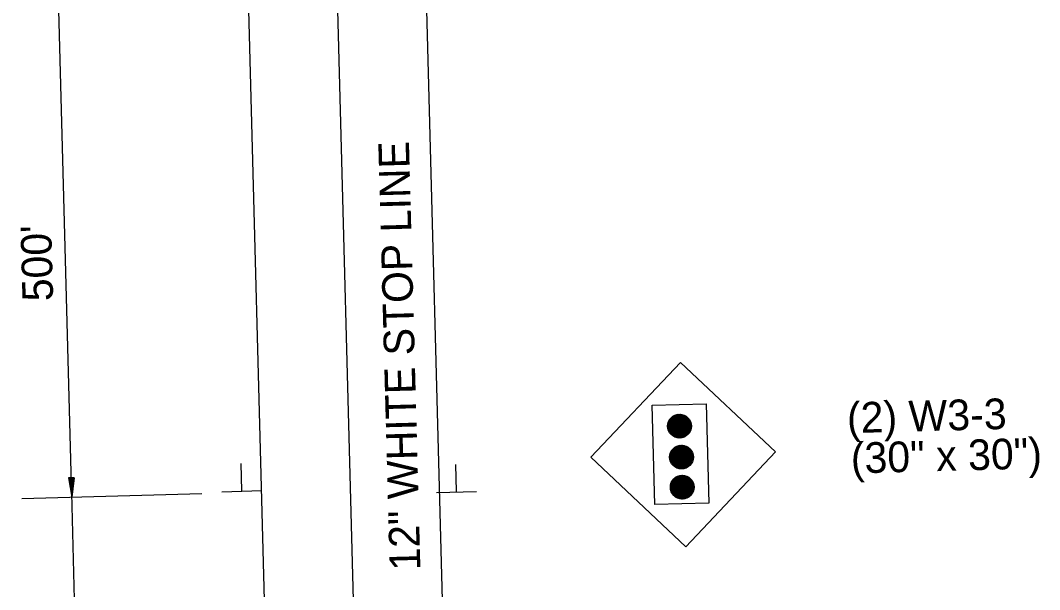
# Model space of a CAD drawing. Extents: x 1929624 to 1932070, y 596315 to 605533.
# Drawn here: x 1929776.5 to 1929980.4, y 598725.3 to 598839.2 of the extents above; entities that cross this region are included whole.
import ezdxf

# ---------------------------------------------------------------- set-up
doc = ezdxf.new("R2010")
doc.units = 0
doc.layers.add('Default', color=7, linetype='Continuous')

msp = doc.modelspace()

# ---------------------------------------------------------------- linework, layer by layer
at = {"layer": 'Default'}
for p, q in [((1929826.09, 598696.32), (1929821.7, 598859.91)), ((1929843.87, 598696.8), (1929839.48, 598860.38)), ((1929861.66, 598697.28), (1929857.27, 598860.86)), ((1929786.82, 598743.86), (1929784.11, 598844.96)), ((1929908.52, 598770.8), (1929890.6, 598751.83)), ((1929927.51, 598752.89), (1929908.52, 598770.8)), ((1929905.96, 598758.03), (1929908.25, 598760.44)), ((1929905.96, 598758.18), (1929908.09, 598760.43)), ((1929905.97, 598757.88), (1929908.39, 598760.44)), ((1929905.98, 598757.75), (1929908.53, 598760.43)), ((1929905.98, 598758.35), (1929907.93, 598760.4)), ((1929906, 598757.62), (1929908.66, 598760.42)), ((1929906.01, 598758.53), (1929907.75, 598760.36)), ((1929906.03, 598757.49), (1929908.78, 598760.4)), ((1929906.06, 598757.38), (1929908.9, 598760.37)), ((1929906.06, 598758.73), (1929907.55, 598760.3)), ((1929906.1, 598757.26), (1929909.01, 598760.34)), ((1929906.14, 598757.16), (1929909.12, 598760.31)), ((1929906.15, 598758.97), (1929907.31, 598760.2)), ((1929906.18, 598757.05), (1929909.23, 598760.27)), ((1929906.23, 598756.95), (1929909.33, 598760.23)), ((1929906.28, 598756.86), (1929909.43, 598760.18)), ((1929906.31, 598759.3), (1929906.99, 598760.02)), ((1929906.34, 598756.77), (1929909.52, 598760.13)), ((1929906.4, 598756.68), (1929909.61, 598760.07)), ((1929906.46, 598756.6), (1929909.7, 598760.01)), ((1929906.53, 598756.51), (1929909.79, 598759.95)), ((1929906.6, 598756.44), (1929909.87, 598759.89)), ((1929906.67, 598756.36), (1929909.95, 598759.82)), ((1929906.74, 598756.29), (1929910.02, 598759.75)), ((1929906.82, 598756.22), (1929910.09, 598759.67)), ((1929906.9, 598756.16), (1929910.16, 598759.6)), ((1929906.99, 598756.1), (1929910.23, 598759.52)), ((1929907.08, 598756.04), (1929910.29, 598759.43)), ((1929907.17, 598755.98), (1929910.35, 598759.34)), ((1929907.26, 598755.93), (1929910.41, 598759.25)), ((1929907.36, 598755.89), (1929910.46, 598759.16)), ((1929907.46, 598755.84), (1929910.51, 598759.06)), ((1929907.57, 598755.8), (1929910.55, 598758.95)), ((1929907.68, 598755.77), (1929910.59, 598758.85)), ((1929907.79, 598755.74), (1929910.63, 598758.73)), ((1929907.91, 598755.71), (1929910.66, 598758.62)), ((1929908.03, 598755.69), (1929910.69, 598758.49)), ((1929908.16, 598755.68), (1929910.71, 598758.36)), ((1929908.3, 598755.67), (1929910.72, 598758.23)), ((1929908.44, 598755.68), (1929910.73, 598758.08)), ((1929908.6, 598755.69), (1929910.72, 598757.93)), ((1929908.76, 598755.71), (1929910.71, 598757.76)), ((1929908.94, 598755.75), (1929910.68, 598757.58)), ((1929909.14, 598755.81), (1929910.63, 598757.38)), ((1929909.38, 598755.91), (1929910.54, 598757.14)), ((1929909.7, 598756.1), (1929910.37, 598756.81)), ((1929906.35, 598751.69), (1929908.77, 598754.24)), ((1929906.35, 598751.83), (1929908.63, 598754.24)), ((1929906.35, 598751.98), (1929908.48, 598754.23)), ((1929906.36, 598752.15), (1929908.31, 598754.21)), ((1929906.37, 598751.55), (1929908.91, 598754.24)), ((1929906.39, 598751.42), (1929909.04, 598754.22)), ((1929906.39, 598752.33), (1929908.13, 598754.17)), ((1929906.41, 598751.3), (1929909.17, 598754.2)), ((1929906.44, 598751.18), (1929909.28, 598754.18)), ((1929906.44, 598752.54), (1929907.93, 598754.11)), ((1929906.48, 598751.07), (1929909.4, 598754.15)), ((1929906.52, 598750.96), (1929909.51, 598754.11)), ((1929906.53, 598752.78), (1929907.7, 598754.01)), ((1929906.57, 598750.86), (1929909.61, 598754.07)), ((1929906.62, 598750.76), (1929909.71, 598754.03)), ((1929906.67, 598750.66), (1929909.81, 598753.98)), ((1929906.7, 598753.1), (1929907.38, 598753.82)), ((1929906.72, 598750.57), (1929909.91, 598753.93)), ((1929906.78, 598750.48), (1929910, 598753.88)), ((1929906.85, 598750.4), (1929910.09, 598753.82)), ((1929906.91, 598750.32), (1929910.17, 598753.76)), ((1929906.98, 598750.24), (1929910.25, 598753.69)), ((1929907.05, 598750.17), (1929910.33, 598753.62)), ((1929907.13, 598750.09), (1929910.41, 598753.55)), ((1929907.21, 598750.03), (1929910.48, 598753.48)), ((1929907.29, 598749.96), (1929910.55, 598753.4)), ((1929907.37, 598749.9), (1929910.61, 598753.32)), ((1929907.46, 598749.84), (1929910.68, 598753.23)), ((1929909.58, 598733.91), (1929890.6, 598751.83)), ((1929907.55, 598749.79), (1929910.73, 598753.15)), ((1929907.65, 598749.74), (1929910.79, 598753.06)), ((1929907.74, 598749.69), (1929910.84, 598752.96)), ((1929907.85, 598749.65), (1929910.89, 598752.86)), ((1929907.95, 598749.61), (1929910.94, 598752.76)), ((1929908.06, 598749.57), (1929910.98, 598752.65)), ((1929908.17, 598749.54), (1929911.01, 598752.54)), ((1929908.29, 598749.52), (1929911.04, 598752.42)), ((1929908.42, 598749.5), (1929911.07, 598752.3)), ((1929908.55, 598749.48), (1929911.09, 598752.17)), ((1929908.68, 598749.48), (1929911.11, 598752.03)), ((1929908.83, 598749.48), (1929911.11, 598751.89)), ((1929908.98, 598749.49), (1929911.11, 598751.73)), ((1929909.15, 598749.51), (1929911.09, 598751.57)), ((1929909.33, 598749.55), (1929911.06, 598751.39)), ((1929909.53, 598749.62), (1929911.01, 598751.18)), ((1929927.51, 598752.89), (1929909.58, 598733.91)), ((1929820.84, 598745.09), (1929820.69, 598750.55)), ((1929863.75, 598744.95), (1929863.6, 598750.41)), ((1929909.76, 598749.71), (1929910.93, 598750.94)), ((1929910.08, 598749.9), (1929910.76, 598750.61)), ((1929787.29, 598747.72), (1929786.14, 598747.68)), ((1929786.14, 598747.68), (1929786.82, 598743.86)), ((1929786.24, 598747.69), (1929786.8, 598744.51)), ((1929786.34, 598747.69), (1929786.79, 598745.16)), ((1929786.43, 598747.69), (1929786.77, 598745.8)), ((1929786.53, 598747.7), (1929786.75, 598746.45)), ((1929786.63, 598747.7), (1929786.73, 598747.09)), ((1929786.81, 598747.7), (1929786.73, 598747.09)), ((1929786.9, 598747.71), (1929786.75, 598746.45)), ((1929787, 598747.71), (1929786.77, 598745.8)), ((1929787.1, 598747.71), (1929786.79, 598745.16)), ((1929787.2, 598747.71), (1929786.8, 598744.51)), ((1929787.29, 598747.72), (1929786.82, 598743.86)), ((1929906.51, 598745.74), (1929908.86, 598748.22)), ((1929906.51, 598745.89), (1929908.71, 598748.21)), ((1929906.52, 598745.6), (1929909, 598748.22)), ((1929906.52, 598746.05), (1929908.55, 598748.19)), ((1929906.54, 598745.47), (1929909.13, 598748.21)), ((1929906.54, 598746.23), (1929908.38, 598748.16)), ((1929906.56, 598745.34), (1929909.26, 598748.19)), ((1929906.58, 598746.42), (1929908.19, 598748.11)), ((1929906.59, 598745.22), (1929909.38, 598748.17)), ((1929906.62, 598745.11), (1929909.5, 598748.14)), ((1929906.65, 598746.64), (1929907.97, 598748.03)), ((1929906.66, 598745), (1929909.61, 598748.11)), ((1929906.7, 598744.89), (1929909.72, 598748.07)), ((1929906.75, 598744.79), (1929909.82, 598748.03)), ((1929906.77, 598746.92), (1929907.7, 598747.9)), ((1929906.8, 598744.69), (1929909.92, 598747.99)), ((1929906.85, 598744.6), (1929910.02, 598747.94)), ((1929906.91, 598744.51), (1929910.11, 598747.88)), ((1929906.97, 598744.42), (1929910.2, 598747.83)), ((1929907.04, 598744.34), (1929910.29, 598747.77)), ((1929907.1, 598744.26), (1929910.37, 598747.71)), ((1929907.17, 598744.18), (1929910.45, 598747.64)), ((1929907.25, 598744.11), (1929910.53, 598747.57)), ((1929907.32, 598744.04), (1929910.6, 598747.5)), ((1929907.4, 598743.97), (1929910.67, 598747.42)), ((1929907.49, 598743.91), (1929910.74, 598747.34)), ((1929907.57, 598743.85), (1929910.8, 598747.26)), ((1929907.66, 598743.79), (1929910.86, 598747.17)), ((1929907.75, 598743.74), (1929910.92, 598747.08)), ((1929824.82, 598745.08), (1929816.82, 598744.86)), ((1929907.85, 598743.69), (1929910.98, 598746.99)), ((1929907.95, 598743.65), (1929911.03, 598746.89)), ((1929908.16, 598743.57), (1929911.12, 598746.69)), ((1929908.27, 598743.54), (1929911.16, 598746.58)), ((1929908.39, 598743.51), (1929911.19, 598746.46)), ((1929908.51, 598743.48), (1929911.22, 598746.34)), ((1929908.64, 598743.47), (1929911.24, 598746.22)), ((1929908.77, 598743.46), (1929911.26, 598746.09)), ((1929908.91, 598743.45), (1929911.27, 598745.95)), ((1929909.06, 598743.46), (1929911.27, 598745.8)), ((1929909.22, 598743.48), (1929911.27, 598745.64)), ((1929909.39, 598743.51), (1929911.24, 598745.47)), ((1929909.57, 598743.55), (1929911.21, 598745.28)), ((1929909.79, 598743.63), (1929911.14, 598745.06)), ((1929776.81, 598743.6), (1929812.82, 598744.56)), ((1929789.48, 598645), (1929786.8, 598744.72)), ((1929867.73, 598744.93), (1929859.73, 598744.72)), ((1929910.05, 598743.76), (1929911.03, 598744.79)), ((1929910.51, 598744.09), (1929910.73, 598744.32))]:
    msp.add_line(p, q, dxfattribs=at)
msp.add_lwpolyline([(1929902.9, 598762.25), (1929913.67, 598762.54), (1929914.2, 598742.67), (1929903.44, 598742.38)], close=True, dxfattribs=at)
for centre in [(1929908.34, 598758.06), (1929908.73, 598751.86), (1929908.89, 598745.84)]:
    msp.add_circle(centre, 2.38, dxfattribs=at)

# ---------------------------------------------------------------- texts
for s, height, rotation, p in [('12" WHITE STOP LINE', 6.1396, 91.5377, (1929856.54, 598729.24)), ("500'", 6.14, 91.5377, (1929783.1, 598783.11)), ('(2) W3-3', 6.14, 1.5377, (1929941.91, 598756.64)), ('(30" x 30")', 6.1396, 1.5377, (1929942.68, 598748.58))]:
    msp.add_text(s, height=height, rotation=rotation, dxfattribs=at).set_placement(p)

doc.saveas('drawing.dxf')
